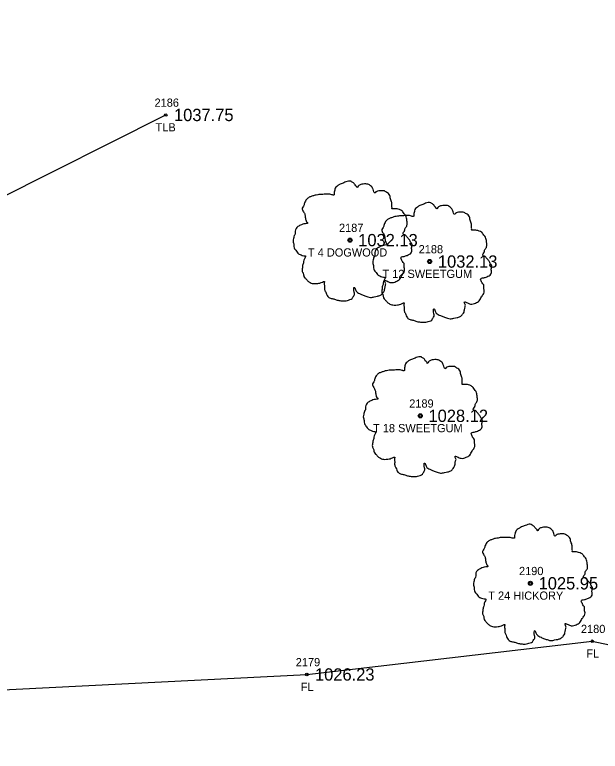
# Model space of a CAD drawing. Extents: x 1578957 to 1581675, y 1115963 to 1120391.
# Drawn here: x 1579963.3 to 1580034.6, y 1117735.8 to 1117825.5 of the extents above; entities that cross this region are included whole.
import ezdxf

# ---------------------------------------------------------------- set-up
doc = ezdxf.new("R2010")
doc.units = 0
for name, color, linetype in [('RD_EX_Fence_Other', 7, 'Continuous'), ('RD_EX_Fence_Other_txCode', 7, 'Continuous'), ('RD_EX_TX_Fence_Other_ELEV', 7, 'Continuous'), ('RD_EX_TX_VEG_ELEV', 7, 'Continuous'), ('RD_EX_VEG', 7, 'Continuous'), ('RD_EX_VEG_txCode', 7, 'Continuous'), ('RD_SMD_Locator', 7, 'Continuous')]:
    doc.layers.add(name, color=color, linetype=linetype)

msp = doc.modelspace()

# ---------------------------------------------------------------- linework, layer by layer
at = {"layer": 'RD_EX_Fence_Other'}
msp.add_lwpolyline([(1579823.104, 1118041.087), (1579819.64, 1117977.762), (1579811.21, 1117936.274), (1579806.912, 1117888.201), (1579805.65, 1117872.977), (1579810.216, 1117834.804), (1579821.355, 1117805.105), (1579835.234, 1117784.194), (1579851.403, 1117768.05), (1579868.554, 1117757.557), (1579908.33, 1117744.227), (1579949.735, 1117742.637), (1579998.853, 1117745.107), (1580033.637, 1117749.157), (1580057.075, 1117744.228), (1580092.078, 1117730.794), (1580117.524, 1117724.619), (1580141.715, 1117727.925), (1580159.983, 1117735.31), (1580192.445, 1117760.446), (1580226.972, 1117787.769), (1580271.309, 1117822.486), (1580302.096, 1117858.032)], dxfattribs=at)
at = {"layer": 'RD_EX_VEG'}
msp.add_line((1579919.197, 1117781.94), (1579981.677, 1117813.265), dxfattribs=at)
for centre, radius in [((1580004.12, 1117798.017), 0.25), ((1580004.108, 1117797.999), 0.0001), ((1580013.826, 1117795.41), 0.25), ((1580013.813, 1117795.391), 0.0001), ((1580012.679, 1117776.616), 0.25), ((1580012.666, 1117776.597), 0.0001), ((1580026.094, 1117756.213), 0.25), ((1580026.081, 1117756.194), 0.0001)]:
    msp.add_circle(centre, radius, dxfattribs=at)
for points in [[(1580004.252, 1117805.185), (1580003.952, 1117805.21), (1580003.628, 1117805.11), (1580003.378, 1117805.01), (1580003.153, 1117804.935), (1580002.928, 1117804.835), (1580002.628, 1117804.66), (1580002.403, 1117804.46), (1580002.278, 1117804.21), (1580002.228, 1117803.985), (1580002.178, 1117803.71), (1580002.178, 1117803.535), (1580002.053, 1117803.51), (1580001.903, 1117803.535), (1580001.653, 1117803.61), (1580001.404, 1117803.61), (1580001.154, 1117803.61), (1580000.804, 1117803.585), (1580000.454, 1117803.585), (1580000.179, 1117803.535), (1579999.854, 1117803.485), (1579999.479, 1117803.36), (1579999.13, 1117803.235), (1579998.83, 1117802.986), (1579998.58, 1117802.511), (1579998.455, 1117802.161), (1579998.305, 1117801.911), (1579998.455, 1117801.461), (1579998.63, 1117801.111), (1579998.655, 1117800.911), (1579998.73, 1117800.487), (1579998.83, 1117800.262), (1579998.955, 1117800.062), (1579998.88, 1117800.037), (1579998.505, 1117799.987), (1579998.205, 1117799.887), (1579997.78, 1117799.662), (1579997.555, 1117799.437), (1579997.455, 1117799.112), (1579997.43, 1117798.762), (1579997.33, 1117798.563), (1579997.255, 1117798.288), (1579997.23, 1117798.213), (1579997.18, 1117797.888), (1579997.28, 1117797.438), (1579997.305, 1117797.088), (1579997.43, 1117796.863), (1579997.58, 1117796.688), (1579997.755, 1117796.438), (1579998.155, 1117796.214), (1579998.48, 1117796.114), (1579998.68, 1117796.089), (1579998.505, 1117795.589), (1579998.455, 1117795.239), (1579998.33, 1117794.839), (1579998.33, 1117794.764), (1579998.28, 1117794.289), (1579998.43, 1117793.964), (1579998.505, 1117793.59), (1579998.68, 1117793.365), (1579998.955, 1117793.065), (1579999.279, 1117792.84), (1579999.779, 1117792.715), (1580000.179, 1117792.74), (1580000.754, 1117792.915), (1580001.004, 1117792.99), (1580000.979, 1117792.815), (1580001.004, 1117792.44), (1580001.004, 1117792.015), (1580001.154, 1117791.691), (1580001.254, 1117791.416), (1580001.404, 1117791.166), (1580001.728, 1117790.941), (1580002.128, 1117790.866), (1580002.553, 1117790.716), (1580003.003, 1117790.641), (1580003.503, 1117790.616), (1580004.102, 1117790.766), (1580004.377, 1117790.891), (1580004.477, 1117791.066), (1580004.677, 1117791.441), (1580004.627, 1117791.666), (1580004.652, 1117792.265), (1580004.752, 1117792.09), (1580004.927, 1117791.74), (1580005.427, 1117791.441), (1580005.827, 1117791.266), (1580006.301, 1117791.116), (1580006.601, 1117791.041), (1580007.076, 1117791.116), (1580007.451, 1117791.191), (1580007.826, 1117791.316), (1580008.126, 1117791.591), (1580008.301, 1117791.865), (1580008.351, 1117792.14), (1580008.425, 1117792.515), (1580008.475, 1117792.69)], [(1580008.475, 1117792.69), (1580008.401, 1117792.865), (1580008.351, 1117793.115), (1580008.425, 1117793.09), (1580008.6, 1117793.04), (1580008.875, 1117792.915), (1580009.1, 1117792.84), (1580009.425, 1117792.865), (1580009.7, 1117792.965), (1580010.15, 1117793.24), (1580010.425, 1117793.715), (1580010.699, 1117794.114), (1580010.774, 1117794.439), (1580010.724, 1117794.664), (1580010.699, 1117795.164), (1580010.5, 1117795.414), (1580010.45, 1117795.539), (1580010.35, 1117795.939), (1580010.425, 1117795.989), (1580010.699, 1117796.039), (1580011.074, 1117796.164), (1580011.349, 1117796.288), (1580011.574, 1117796.463), (1580011.649, 1117796.688), (1580011.624, 1117797.088), (1580011.674, 1117797.488), (1580011.599, 1117797.638), (1580011.499, 1117797.788), (1580011.424, 1117797.988), (1580011.274, 1117798.138), (1580011.174, 1117798.288), (1580011.074, 1117798.388), (1580010.949, 1117798.538), (1580010.774, 1117798.662), (1580010.625, 1117798.712), (1580010.575, 1117798.862), (1580010.724, 1117799.062), (1580010.774, 1117799.162), (1580010.799, 1117799.387), (1580011.024, 1117799.737), (1580011.074, 1117800.137), (1580011.024, 1117800.562), (1580010.974, 1117800.837), (1580010.824, 1117801.111), (1580010.625, 1117801.361), (1580010.5, 1117801.536), (1580010.325, 1117801.661), (1580010, 1117801.786), (1580009.75, 1117801.836), (1580009.4, 1117801.836), (1580009.2, 1117801.886), (1580009.225, 1117801.936), (1580009.225, 1117802.086), (1580009.225, 1117802.361), (1580009.15, 1117802.811), (1580009, 1117803.31), (1580009, 1117803.335), (1580008.9, 1117803.585), (1580008.675, 1117803.785), (1580008.5, 1117803.885), (1580008.301, 1117804.01), (1580008.051, 1117804.035), (1580007.751, 1117804.035), (1580007.476, 1117803.985), (1580007.276, 1117803.885), (1580007.101, 1117803.76), (1580007.026, 1117803.91), (1580006.926, 1117804.21), (1580006.876, 1117804.36), (1580006.726, 1117804.535), (1580006.501, 1117804.735), (1580006.051, 1117804.86), (1580005.427, 1117804.785), (1580005.127, 1117804.585), (1580004.977, 1117804.41), (1580004.927, 1117804.535), (1580004.727, 1117804.735), (1580004.627, 1117804.91), (1580004.452, 1117805.035), (1580004.302, 1117805.135), (1580004.202, 1117805.185)], [(1580013.958, 1117802.578), (1580013.658, 1117802.603), (1580013.333, 1117802.503), (1580013.083, 1117802.403), (1580012.858, 1117802.328), (1580012.634, 1117802.228), (1580012.334, 1117802.053), (1580012.109, 1117801.853), (1580011.984, 1117801.603), (1580011.934, 1117801.378), (1580011.884, 1117801.103), (1580011.884, 1117800.928), (1580011.759, 1117800.903), (1580011.609, 1117800.928), (1580011.359, 1117801.003), (1580011.109, 1117801.003), (1580010.859, 1117801.003), (1580010.509, 1117800.978), (1580010.16, 1117800.978), (1580009.885, 1117800.928), (1580009.56, 1117800.878), (1580009.185, 1117800.753), (1580008.835, 1117800.628), (1580008.535, 1117800.378), (1580008.285, 1117799.904), (1580008.16, 1117799.554), (1580008.011, 1117799.304), (1580008.16, 1117798.854), (1580008.335, 1117798.504), (1580008.36, 1117798.304), (1580008.435, 1117797.88), (1580008.535, 1117797.655), (1580008.66, 1117797.455), (1580008.585, 1117797.43), (1580008.21, 1117797.38), (1580007.911, 1117797.28), (1580007.486, 1117797.055), (1580007.261, 1117796.83), (1580007.161, 1117796.505), (1580007.136, 1117796.155), (1580007.036, 1117795.955), (1580006.961, 1117795.681), (1580006.936, 1117795.606), (1580006.886, 1117795.281), (1580006.986, 1117794.831), (1580007.011, 1117794.481), (1580007.136, 1117794.256), (1580007.286, 1117794.081), (1580007.461, 1117793.831), (1580007.861, 1117793.606), (1580008.185, 1117793.506), (1580008.385, 1117793.482), (1580008.21, 1117792.982), (1580008.16, 1117792.632), (1580008.036, 1117792.232), (1580008.036, 1117792.157), (1580007.986, 1117791.682), (1580008.135, 1117791.357), (1580008.21, 1117790.983), (1580008.385, 1117790.758), (1580008.66, 1117790.458), (1580008.985, 1117790.233), (1580009.485, 1117790.108), (1580009.885, 1117790.133), (1580010.46, 1117790.308), (1580010.709, 1117790.383), (1580010.684, 1117790.208), (1580010.709, 1117789.833), (1580010.709, 1117789.408), (1580010.859, 1117789.083), (1580010.959, 1117788.809), (1580011.109, 1117788.559), (1580011.434, 1117788.334), (1580011.834, 1117788.259), (1580012.259, 1117788.109), (1580012.709, 1117788.034), (1580013.208, 1117788.009), (1580013.808, 1117788.159), (1580014.083, 1117788.284), (1580014.183, 1117788.459), (1580014.383, 1117788.834), (1580014.333, 1117789.058), (1580014.358, 1117789.658), (1580014.458, 1117789.483), (1580014.633, 1117789.133), (1580015.132, 1117788.834), (1580015.532, 1117788.659), (1580016.007, 1117788.509), (1580016.307, 1117788.434), (1580016.782, 1117788.509), (1580017.157, 1117788.584), (1580017.531, 1117788.709), (1580017.831, 1117788.983), (1580018.006, 1117789.258), (1580018.056, 1117789.533), (1580018.131, 1117789.908), (1580018.181, 1117790.083)], [(1580018.181, 1117790.083), (1580018.106, 1117790.258), (1580018.056, 1117790.508), (1580018.131, 1117790.483), (1580018.306, 1117790.433), (1580018.581, 1117790.308), (1580018.806, 1117790.233), (1580019.131, 1117790.258), (1580019.406, 1117790.358), (1580019.855, 1117790.633), (1580020.13, 1117791.108), (1580020.405, 1117791.507), (1580020.48, 1117791.832), (1580020.43, 1117792.057), (1580020.405, 1117792.557), (1580020.205, 1117792.807), (1580020.155, 1117792.932), (1580020.055, 1117793.332), (1580020.13, 1117793.382), (1580020.405, 1117793.432), (1580020.78, 1117793.556), (1580021.055, 1117793.681), (1580021.28, 1117793.856), (1580021.355, 1117794.081), (1580021.33, 1117794.481), (1580021.38, 1117794.881), (1580021.305, 1117795.031), (1580021.205, 1117795.181), (1580021.13, 1117795.381), (1580020.98, 1117795.531), (1580020.88, 1117795.681), (1580020.78, 1117795.78), (1580020.655, 1117795.93), (1580020.48, 1117796.055), (1580020.33, 1117796.105), (1580020.28, 1117796.255), (1580020.43, 1117796.455), (1580020.48, 1117796.555), (1580020.505, 1117796.78), (1580020.73, 1117797.13), (1580020.78, 1117797.53), (1580020.73, 1117797.955), (1580020.68, 1117798.229), (1580020.53, 1117798.504), (1580020.33, 1117798.754), (1580020.205, 1117798.929), (1580020.03, 1117799.054), (1580019.705, 1117799.179), (1580019.456, 1117799.229), (1580019.106, 1117799.229), (1580018.906, 1117799.279), (1580018.931, 1117799.329), (1580018.931, 1117799.479), (1580018.931, 1117799.754), (1580018.856, 1117800.204), (1580018.706, 1117800.703), (1580018.706, 1117800.728), (1580018.606, 1117800.978), (1580018.381, 1117801.178), (1580018.206, 1117801.278), (1580018.006, 1117801.403), (1580017.756, 1117801.428), (1580017.456, 1117801.428), (1580017.182, 1117801.378), (1580016.982, 1117801.278), (1580016.807, 1117801.153), (1580016.732, 1117801.303), (1580016.632, 1117801.603), (1580016.582, 1117801.753), (1580016.432, 1117801.928), (1580016.207, 1117802.128), (1580015.757, 1117802.253), (1580015.132, 1117802.178), (1580014.833, 1117801.978), (1580014.683, 1117801.803), (1580014.633, 1117801.928), (1580014.433, 1117802.128), (1580014.333, 1117802.303), (1580014.158, 1117802.428), (1580014.008, 1117802.528), (1580013.908, 1117802.578)], [(1580012.811, 1117783.783), (1580012.511, 1117783.808), (1580012.186, 1117783.708), (1580011.936, 1117783.609), (1580011.711, 1117783.534), (1580011.486, 1117783.434), (1580011.186, 1117783.259), (1580010.962, 1117783.059), (1580010.837, 1117782.809), (1580010.787, 1117782.584), (1580010.737, 1117782.309), (1580010.737, 1117782.134), (1580010.612, 1117782.109), (1580010.462, 1117782.134), (1580010.212, 1117782.209), (1580009.962, 1117782.209), (1580009.712, 1117782.209), (1580009.362, 1117782.184), (1580009.012, 1117782.184), (1580008.738, 1117782.134), (1580008.413, 1117782.084), (1580008.038, 1117781.959), (1580007.688, 1117781.834), (1580007.388, 1117781.584), (1580007.138, 1117781.11), (1580007.013, 1117780.76), (1580006.863, 1117780.51), (1580007.013, 1117780.06), (1580007.188, 1117779.71), (1580007.213, 1117779.51), (1580007.288, 1117779.086), (1580007.388, 1117778.861), (1580007.513, 1117778.661), (1580007.438, 1117778.636), (1580007.063, 1117778.586), (1580006.763, 1117778.486), (1580006.339, 1117778.261), (1580006.114, 1117778.036), (1580006.014, 1117777.711), (1580005.989, 1117777.361), (1580005.889, 1117777.161), (1580005.814, 1117776.886), (1580005.789, 1117776.811), (1580005.739, 1117776.487), (1580005.839, 1117776.037), (1580005.864, 1117775.687), (1580005.989, 1117775.462), (1580006.139, 1117775.287), (1580006.314, 1117775.037), (1580006.713, 1117774.812), (1580007.038, 1117774.712), (1580007.238, 1117774.687), (1580007.063, 1117774.188), (1580007.013, 1117773.838), (1580006.888, 1117773.438), (1580006.888, 1117773.363), (1580006.838, 1117772.888), (1580006.988, 1117772.563), (1580007.063, 1117772.189), (1580007.238, 1117771.964), (1580007.513, 1117771.664), (1580007.838, 1117771.439), (1580008.338, 1117771.314), (1580008.738, 1117771.339), (1580009.312, 1117771.514), (1580009.562, 1117771.589), (1580009.537, 1117771.414), (1580009.562, 1117771.039), (1580009.562, 1117770.614), (1580009.712, 1117770.289), (1580009.812, 1117770.014), (1580009.962, 1117769.765), (1580010.287, 1117769.54), (1580010.687, 1117769.465), (1580011.111, 1117769.315), (1580011.561, 1117769.24), (1580012.061, 1117769.215), (1580012.661, 1117769.365), (1580012.936, 1117769.49), (1580013.036, 1117769.665), (1580013.236, 1117770.039), (1580013.186, 1117770.264), (1580013.211, 1117770.864), (1580013.31, 1117770.689), (1580013.485, 1117770.339), (1580013.985, 1117770.039), (1580014.385, 1117769.865), (1580014.86, 1117769.715), (1580015.16, 1117769.64), (1580015.634, 1117769.715), (1580016.009, 1117769.79), (1580016.384, 1117769.915), (1580016.684, 1117770.189), (1580016.859, 1117770.464), (1580016.909, 1117770.739), (1580016.984, 1117771.114), (1580017.034, 1117771.289)], [(1580017.034, 1117771.289), (1580016.959, 1117771.464), (1580016.909, 1117771.714), (1580016.984, 1117771.689), (1580017.159, 1117771.639), (1580017.434, 1117771.514), (1580017.659, 1117771.439), (1580017.983, 1117771.464), (1580018.258, 1117771.564), (1580018.708, 1117771.839), (1580018.983, 1117772.313), (1580019.258, 1117772.713), (1580019.333, 1117773.038), (1580019.283, 1117773.263), (1580019.258, 1117773.763), (1580019.058, 1117774.013), (1580019.008, 1117774.138), (1580018.908, 1117774.537), (1580018.983, 1117774.587), (1580019.258, 1117774.637), (1580019.633, 1117774.762), (1580019.908, 1117774.887), (1580020.133, 1117775.062), (1580020.207, 1117775.287), (1580020.183, 1117775.687), (1580020.232, 1117776.087), (1580020.158, 1117776.237), (1580020.058, 1117776.387), (1580019.983, 1117776.587), (1580019.833, 1117776.736), (1580019.733, 1117776.886), (1580019.633, 1117776.986), (1580019.508, 1117777.136), (1580019.333, 1117777.261), (1580019.183, 1117777.311), (1580019.133, 1117777.461), (1580019.283, 1117777.661), (1580019.333, 1117777.761), (1580019.358, 1117777.986), (1580019.583, 1117778.336), (1580019.633, 1117778.736), (1580019.583, 1117779.16), (1580019.533, 1117779.435), (1580019.383, 1117779.71), (1580019.183, 1117779.96), (1580019.058, 1117780.135), (1580018.883, 1117780.26), (1580018.558, 1117780.385), (1580018.308, 1117780.435), (1580017.958, 1117780.435), (1580017.759, 1117780.485), (1580017.784, 1117780.535), (1580017.784, 1117780.685), (1580017.784, 1117780.96), (1580017.709, 1117781.409), (1580017.559, 1117781.909), (1580017.559, 1117781.934), (1580017.459, 1117782.184), (1580017.234, 1117782.384), (1580017.059, 1117782.484), (1580016.859, 1117782.609), (1580016.609, 1117782.634), (1580016.309, 1117782.634), (1580016.034, 1117782.584), (1580015.834, 1117782.484), (1580015.659, 1117782.359), (1580015.584, 1117782.509), (1580015.485, 1117782.809), (1580015.435, 1117782.959), (1580015.285, 1117783.134), (1580015.06, 1117783.334), (1580014.61, 1117783.459), (1580013.985, 1117783.384), (1580013.685, 1117783.184), (1580013.535, 1117783.009), (1580013.485, 1117783.134), (1580013.285, 1117783.334), (1580013.186, 1117783.509), (1580013.011, 1117783.634), (1580012.861, 1117783.733), (1580012.761, 1117783.783)], [(1580026.226, 1117763.38), (1580025.926, 1117763.405), (1580025.601, 1117763.305), (1580025.351, 1117763.205), (1580025.126, 1117763.13), (1580024.901, 1117763.03), (1580024.601, 1117762.856), (1580024.376, 1117762.656), (1580024.251, 1117762.406), (1580024.201, 1117762.181), (1580024.152, 1117761.906), (1580024.152, 1117761.731), (1580024.027, 1117761.706), (1580023.877, 1117761.731), (1580023.627, 1117761.806), (1580023.377, 1117761.806), (1580023.127, 1117761.806), (1580022.777, 1117761.781), (1580022.427, 1117761.781), (1580022.152, 1117761.731), (1580021.828, 1117761.681), (1580021.453, 1117761.556), (1580021.103, 1117761.431), (1580020.803, 1117761.181), (1580020.553, 1117760.707), (1580020.428, 1117760.357), (1580020.278, 1117760.107), (1580020.428, 1117759.657), (1580020.603, 1117759.307), (1580020.628, 1117759.107), (1580020.703, 1117758.682), (1580020.803, 1117758.458), (1580020.928, 1117758.258), (1580020.853, 1117758.233), (1580020.478, 1117758.183), (1580020.178, 1117758.083), (1580019.753, 1117757.858), (1580019.529, 1117757.633), (1580019.429, 1117757.308), (1580019.404, 1117756.958), (1580019.304, 1117756.758), (1580019.229, 1117756.483), (1580019.204, 1117756.408), (1580019.154, 1117756.084), (1580019.254, 1117755.634), (1580019.279, 1117755.284), (1580019.404, 1117755.059), (1580019.554, 1117754.884), (1580019.728, 1117754.634), (1580020.128, 1117754.409), (1580020.453, 1117754.309), (1580020.653, 1117754.284), (1580020.478, 1117753.785), (1580020.428, 1117753.435), (1580020.303, 1117753.035), (1580020.303, 1117752.96), (1580020.253, 1117752.485), (1580020.403, 1117752.16), (1580020.478, 1117751.785), (1580020.653, 1117751.561), (1580020.928, 1117751.261), (1580021.253, 1117751.036), (1580021.753, 1117750.911), (1580022.152, 1117750.936), (1580022.727, 1117751.111), (1580022.977, 1117751.186), (1580022.952, 1117751.011), (1580022.977, 1117750.636), (1580022.977, 1117750.211), (1580023.127, 1117749.886), (1580023.227, 1117749.611), (1580023.377, 1117749.361), (1580023.702, 1117749.137), (1580024.102, 1117749.062), (1580024.526, 1117748.912), (1580024.976, 1117748.837), (1580025.476, 1117748.812), (1580026.076, 1117748.962), (1580026.351, 1117749.087), (1580026.451, 1117749.262), (1580026.65, 1117749.636), (1580026.6, 1117749.861), (1580026.625, 1117750.461), (1580026.725, 1117750.286), (1580026.9, 1117749.936), (1580027.4, 1117749.636), (1580027.8, 1117749.461), (1580028.275, 1117749.311), (1580028.575, 1117749.237), (1580029.049, 1117749.311), (1580029.424, 1117749.386), (1580029.799, 1117749.511), (1580030.099, 1117749.786), (1580030.274, 1117750.061), (1580030.324, 1117750.336), (1580030.399, 1117750.711), (1580030.449, 1117750.886)], [(1580030.449, 1117750.886), (1580030.374, 1117751.061), (1580030.324, 1117751.311), (1580030.399, 1117751.286), (1580030.574, 1117751.236), (1580030.849, 1117751.111), (1580031.074, 1117751.036), (1580031.398, 1117751.061), (1580031.673, 1117751.161), (1580032.123, 1117751.436), (1580032.398, 1117751.91), (1580032.673, 1117752.31), (1580032.748, 1117752.635), (1580032.698, 1117752.86), (1580032.673, 1117753.36), (1580032.473, 1117753.61), (1580032.423, 1117753.735), (1580032.323, 1117754.134), (1580032.398, 1117754.184), (1580032.673, 1117754.234), (1580033.048, 1117754.359), (1580033.323, 1117754.484), (1580033.547, 1117754.659), (1580033.622, 1117754.884), (1580033.597, 1117755.284), (1580033.647, 1117755.684), (1580033.572, 1117755.834), (1580033.472, 1117755.984), (1580033.397, 1117756.184), (1580033.248, 1117756.333), (1580033.148, 1117756.483), (1580033.048, 1117756.583), (1580032.923, 1117756.733), (1580032.748, 1117756.858), (1580032.598, 1117756.908), (1580032.548, 1117757.058), (1580032.698, 1117757.258), (1580032.748, 1117757.358), (1580032.773, 1117757.583), (1580032.998, 1117757.933), (1580033.048, 1117758.333), (1580032.998, 1117758.757), (1580032.948, 1117759.032), (1580032.798, 1117759.307), (1580032.598, 1117759.557), (1580032.473, 1117759.732), (1580032.298, 1117759.857), (1580031.973, 1117759.982), (1580031.723, 1117760.032), (1580031.373, 1117760.032), (1580031.173, 1117760.082), (1580031.198, 1117760.132), (1580031.198, 1117760.282), (1580031.198, 1117760.557), (1580031.123, 1117761.006), (1580030.974, 1117761.506), (1580030.974, 1117761.531), (1580030.874, 1117761.781), (1580030.649, 1117761.981), (1580030.474, 1117762.081), (1580030.274, 1117762.206), (1580030.024, 1117762.231), (1580029.724, 1117762.231), (1580029.449, 1117762.181), (1580029.249, 1117762.081), (1580029.074, 1117761.956), (1580028.999, 1117762.106), (1580028.899, 1117762.406), (1580028.849, 1117762.556), (1580028.7, 1117762.731), (1580028.475, 1117762.931), (1580028.025, 1117763.055), (1580027.4, 1117762.981), (1580027.1, 1117762.781), (1580026.95, 1117762.606), (1580026.9, 1117762.731), (1580026.7, 1117762.931), (1580026.6, 1117763.105), (1580026.426, 1117763.23), (1580026.276, 1117763.33), (1580026.176, 1117763.38)]]:
    msp.add_spline(points, degree=3, dxfattribs=at)
at = {"layer": 'RD_SMD_Locator'}
for centre in [(1579981.677, 1117813.265), (1580004.12, 1117798.017), (1580013.826, 1117795.41), (1580012.679, 1117776.616), (1580026.094, 1117756.213), (1580033.637, 1117749.157), (1579998.853, 1117745.107)]:
    msp.add_circle(centre, 0.15, dxfattribs=at)

# ---------------------------------------------------------------- texts
at = {"layer": 'RD_EX_Fence_Other_txCode'}
for s, p in [('2180', (1580032.251, 1117750.157)), ('FL', (1580032.905, 1117747.157)), ('2179', (1579997.507, 1117746.107)), ('FL', (1579998.121, 1117743.107))]:
    msp.add_text(s, height=1, dxfattribs=at).set_placement(p)
at = {"layer": 'RD_EX_TX_Fence_Other_ELEV'}
msp.add_text('1026.23', height=1.5, dxfattribs=at).set_placement((1579999.853, 1117744.357))
at = {"layer": 'RD_EX_TX_VEG_ELEV'}
for s, p in [('1037.75', (1579982.677, 1117812.515)), ('1032.13', (1580005.12, 1117797.267)), ('1032.13', (1580014.826, 1117794.66)), ('1028.12', (1580013.679, 1117775.866)), ('1025.95', (1580027.094, 1117755.463))]:
    msp.add_text(s, height=1.5, dxfattribs=at).set_placement(p)
at = {"layer": 'RD_EX_VEG_txCode'}
for s, p in [('2186', (1579980.307, 1117814.265)), ('TLB', (1579980.433, 1117811.265)), ('2187', (1580002.774, 1117799.017)), ('T 4 DOGWOOD', (1579998.994, 1117796.017)), ('2188', (1580012.48, 1117796.41)), ('T 12 SWEETGUM', (1580008.07, 1117793.41)), ('2189', (1580011.332, 1117777.616)), ('T 18 SWEETGUM', (1580006.923, 1117774.616)), ('2190', (1580024.708, 1117757.213)), ('T 24 HICKORY', (1580020.96, 1117754.213))]:
    msp.add_text(s, height=1, dxfattribs=at).set_placement(p)

doc.saveas('drawing.dxf')
